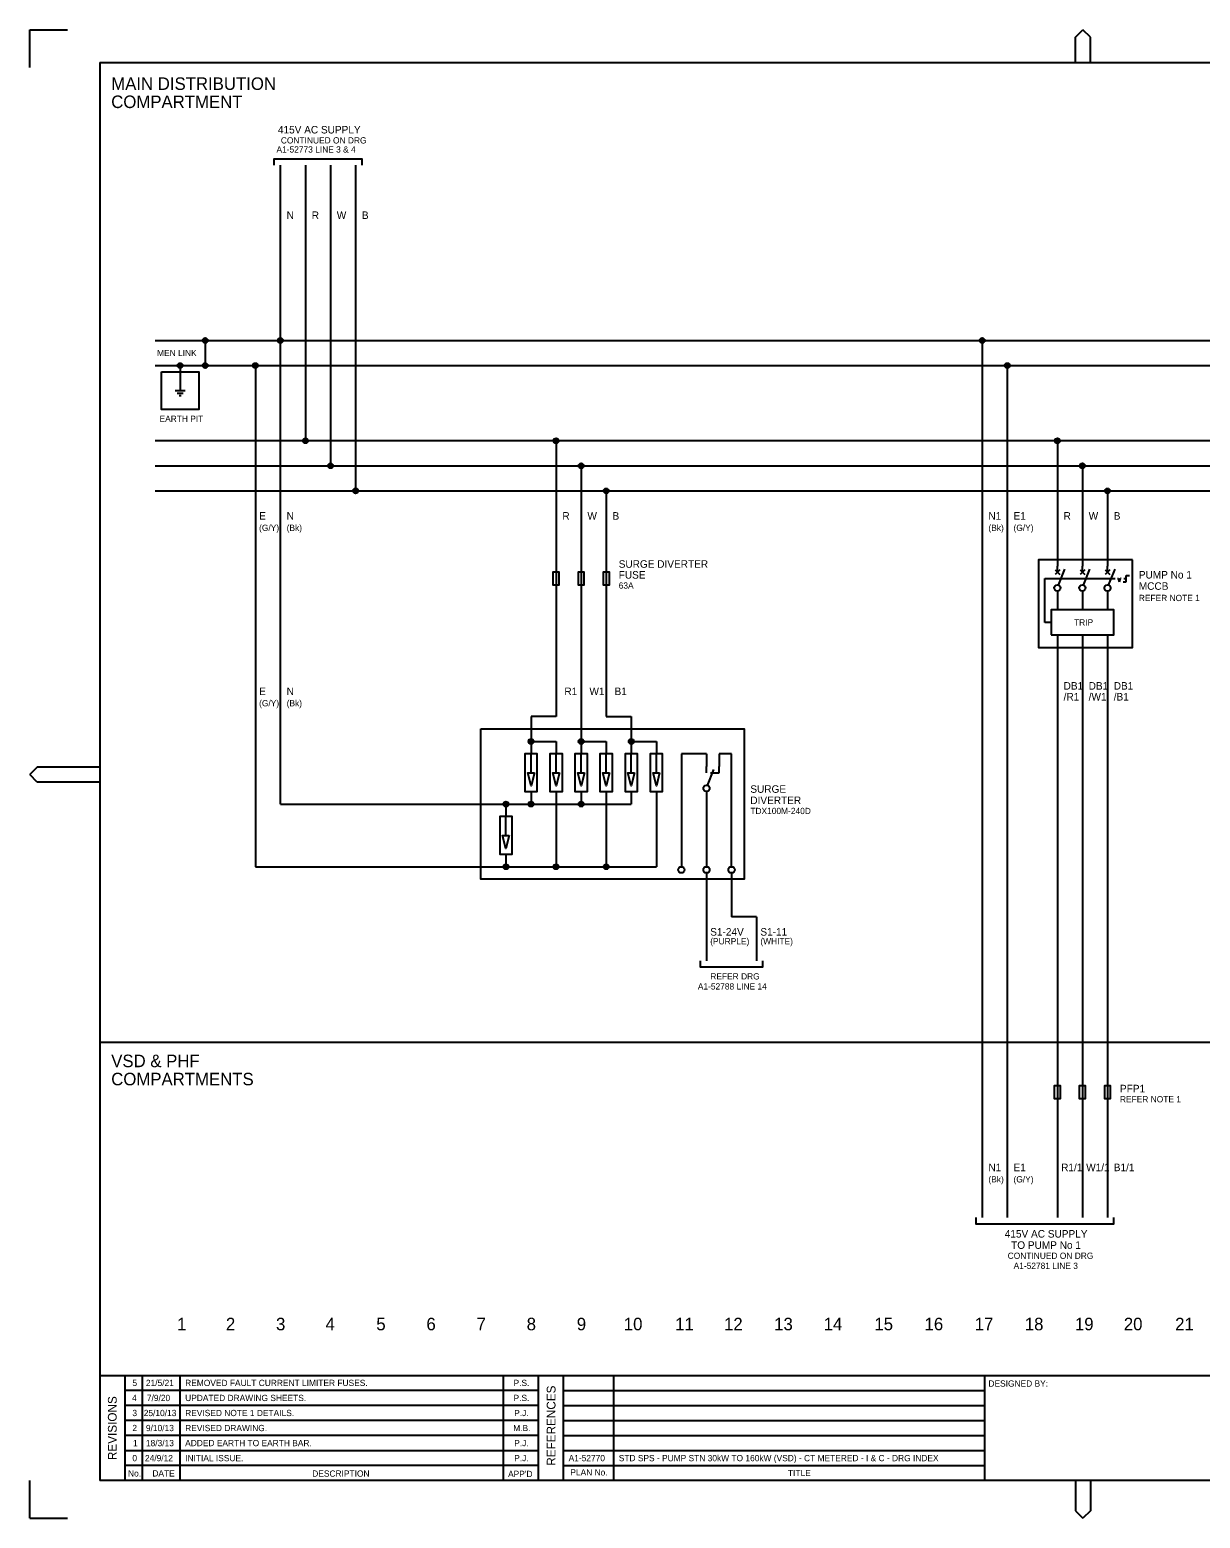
# Model space of a CAD drawing. Extents: x 0 to 841, y 0 to 594.
# Drawn here: x 0 to 467, y 0 to 594 of the extents above; entities that cross this region are included whole.
import ezdxf

# ---------------------------------------------------------------- set-up
doc = ezdxf.new("R2010")
doc.units = 0
for name, color, linetype in [('A1BORDER', 7, 'Continuous'), ('Level 1', 7, 'Continuous'), ('Level 10', 7, 'Continuous')]:
    doc.layers.add(name, color=color, linetype=linetype)

msp = doc.modelspace()

# ---------------------------------------------------------------- linework, layer by layer
at = {"layer": 'A1BORDER'}
for p, q in [((0, 594), (15, 594)), ((0, 579), (0, 594)), ((417.19, 591), (420.19, 594)), ((423.19, 591), (420.19, 594)), ((417.19, 581), (417.19, 591)), ((423.19, 581), (423.19, 591)), ((28, 581), (829, 581)), ((28, 581), (28, 15)), ((3, 299.76), (0, 296.76)), ((28, 299.76), (3, 299.76)), ((3, 293.76), (0, 296.76)), ((28, 293.76), (3, 293.76)), ((28, 57), (829, 57)), ((38, 15), (38, 57)), ((45, 15), (45, 57)), ((60, 15), (60, 57)), ((189, 15), (189, 57)), ((203, 15), (203, 57)), ((213, 15), (213, 57)), ((233, 15), (233, 57)), ((381, 15), (381, 57)), ((203, 51), (38, 51)), ((213, 51), (381, 51)), ((203, 45), (38, 45)), ((213, 45), (381, 45)), ((203, 39), (38, 39)), ((213, 39), (381, 39)), ((203, 33), (38, 33)), ((213, 33), (381, 33)), ((38, 27), (203, 27)), ((213, 27), (381, 27)), ((203, 21), (38, 21)), ((213, 21), (381, 21)), ((0, 0), (0, 15)), ((829, 15), (28, 15)), ((417.19, 15), (417.19, 3)), ((423.19, 15), (423.19, 3)), ((0, 0), (15, 0)), ((417.19, 3), (420.19, 0)), ((423.19, 3), (420.19, 0))]:
    msp.add_line(p, q, dxfattribs=at)
at = {"layer": 'Level 1'}
for p, q in [((100, 285), (100, 540)), ((110, 540), (110, 430)), ((120, 540), (120, 420)), ((130, 540), (130, 410)), ((50, 470), (800, 470)), ((70, 470), (70, 460)), ((380, 470), (380, 120)), ((50, 460), (800, 460)), ((60, 460), (60, 450)), ((90, 460.00001), (90, 260)), ((390, 460), (390, 120)), ((800, 430), (50, 430)), ((210, 430), (210, 320)), ((410, 430), (410, 380)), ((50, 420), (800, 420)), ((220, 420), (220, 305.00001)), ((420, 420), (420, 380)), ((50, 410), (800, 410)), ((230, 410), (230, 320)), ((430, 410), (430, 380)), ((405, 357.5), (405, 375)), ((405, 375), (411.5, 375)), ((409.06, 378.44), (410.94, 376.56)), ((410.94, 378.44), (409.06, 376.56)), ((410, 377.5), (410, 380)), ((410.46, 372.41), (413, 378.75)), ((411.5, 375), (431.5, 375)), ((419.06, 378.44), (420.94, 376.56)), ((420.94, 378.44), (419.06, 376.56)), ((420, 377.5), (420, 380)), ((420.46, 372.41), (423, 378.75)), ((429.06, 378.44), (430.94, 376.56)), ((430.94, 378.44), (429.06, 376.56)), ((430, 377.5), (430, 380)), ((430.46, 372.41), (433, 378.75)), ((410, 370), (410, 362.5)), ((420, 370), (420, 362.5)), ((430, 370), (430, 362.5)), ((407.5, 357.5), (405, 357.5)), ((410, 352.5), (410, 120)), ((420, 352.5), (420, 120)), ((430, 352.5), (430, 120)), ((210, 320.00001), (200, 320.00001)), ((200, 320.00001), (200, 305)), ((230, 320.00001), (240, 320.00001)), ((240, 320.00001), (240, 305.00001)), ((200, 310.00001), (210, 310.00001)), ((210, 310.00001), (210, 305)), ((220, 310.00002), (230, 310.00002)), ((230, 310.00002), (230, 305.00001)), ((240, 310.00002), (250, 310.00002)), ((250, 310.00002), (250, 305.00001)), ((200, 297.5), (200, 305)), ((210, 297.5), (210, 305)), ((220, 297.50001), (220, 305.00001)), ((230, 297.50001), (230, 305.00001)), ((240, 297.50001), (240, 305.00001)), ((250, 297.50001), (250, 305.00001)), ((260, 305), (260, 260)), ((270, 305), (260, 305)), ((270, 305), (270, 300)), ((280, 305), (275, 305)), ((275, 305), (275, 300)), ((280, 259.99999), (280, 305)), ((200, 290), (200, 285)), ((210, 290), (210, 260)), ((220, 290.00001), (220, 285.00001)), ((230, 290.00001), (230, 260)), ((240, 290.00001), (240, 285)), ((250, 290.00001), (250, 260)), ((270, 290), (270, 259.99999)), ((100, 285), (240, 285)), ((190, 285), (190, 280)), ((190, 272.5), (190, 280)), ((190, 265), (190, 260)), ((90, 260), (250, 260)), ((270, 257.49999), (270, 222.5)), ((280, 257.5), (280, 240)), ((290, 239.99999), (280, 239.99999)), ((290, 239.99999), (290, 222.49999)), ((28, 190), (829, 190))]:
    msp.add_line(p, q, dxfattribs=at)
for points in [[(97.5, 540), (97.5, 542.5), (132.5, 542.5), (132.5, 540)], [(267.5, 222.5), (267.5, 220), (292.5, 220), (292.5, 222.5)], [(377.5, 120), (377.5, 117.5), (432.5, 117.5), (432.5, 120)]]:
    msp.add_lwpolyline(points, dxfattribs=at)
for points in [[(52.5, 457.5), (67.5, 457.5), (67.5, 442.5), (52.5, 442.5)], [(440, 382.5), (402.5, 382.5), (402.5, 347.5), (440, 347.5)], [(407.5, 352.5), (432.5, 352.5), (432.5, 362.5), (407.5, 362.5)], [(180, 315), (285, 315), (285, 254.99999), (180, 254.99999)], [(201.32, 297.5), (200, 292.26), (198.68, 297.5)], [(211.32, 297.5), (210, 292.26), (208.68, 297.5)], [(221.32, 297.50001), (220, 292.26001), (218.68, 297.50001)], [(231.32, 297.50001), (230, 292.26001), (228.68, 297.50001)], [(241.32, 297.50001), (240, 292.26001), (238.68, 297.50001)], [(251.32, 297.50001), (250, 292.26001), (248.68, 297.50001)], [(191.32, 272.5), (190, 267.26), (188.68, 272.5)]]:
    msp.add_lwpolyline(points, close=True, dxfattribs=at)
for centre in [(410, 371.25), (420, 371.25), (430, 371.25)]:
    msp.add_circle(centre, 1.25, dxfattribs=at)
at = {"layer": 'Level 10'}
for p, q in [((69.01, 470.1), (70.99, 470.1)), ((69.02, 469.8), (70.98, 469.8)), ((69.08, 470.4), (70.92, 470.4)), ((69.13, 469.5), (70.87, 469.5)), ((69.29, 470.7), (70.71, 470.7)), ((70, 471), (70, 471)), ((99.01, 470.1), (100.99, 470.1)), ((99.02, 469.8), (100.98, 469.8)), ((99.08, 470.4), (100.92, 470.4)), ((99.13, 469.5), (100.87, 469.5)), ((99.29, 470.7), (100.71, 470.7)), ((100, 471), (100, 471)), ((379.01, 470.1), (380.99, 470.1)), ((379.02, 469.8), (380.98, 469.8)), ((379.08, 470.4), (380.92, 470.4)), ((379.13, 469.5), (380.87, 469.5)), ((379.29, 470.7), (380.71, 470.7)), ((380, 471), (380, 471)), ((69.4, 469.2), (70.6, 469.2)), ((99.4, 469.2), (100.6, 469.2)), ((379.4, 469.2), (380.6, 469.2)), ((59.01, 460.1), (60.99, 460.1)), ((59.02, 459.8), (60.98, 459.8)), ((59.08, 460.4), (60.92, 460.4)), ((59.13, 459.5), (60.87, 459.5)), ((59.29, 460.7), (60.71, 460.7)), ((59.4, 459.2), (60.6, 459.2)), ((60, 461), (60, 461)), ((69.01, 460.1), (70.99, 460.1)), ((69.02, 459.8), (70.98, 459.8)), ((69.08, 460.4), (70.92, 460.4)), ((69.13, 459.5), (70.87, 459.5)), ((69.29, 460.7), (70.71, 460.7)), ((69.4, 459.2), (70.6, 459.2)), ((70, 461), (70, 461)), ((89.01, 460.10001), (90.99, 460.10001)), ((89.02, 459.80001), (90.98, 459.80001)), ((89.08, 460.40001), (90.92, 460.40001)), ((89.13, 459.50001), (90.87, 459.50001)), ((89.29, 460.70001), (90.71, 460.70001)), ((89.4, 459.20001), (90.6, 459.20001)), ((90, 461.00001), (90, 461.00001)), ((389.01, 460.1), (390.99, 460.1)), ((389.02, 459.8), (390.98, 459.8)), ((389.08, 460.4), (390.92, 460.4)), ((389.13, 459.5), (390.87, 459.5)), ((389.29, 460.7), (390.71, 460.7)), ((389.4, 459.2), (390.6, 459.2)), ((390, 461), (390, 461)), ((58, 450), (62, 450)), ((58.8, 449), (61.2, 449)), ((59.6, 448), (60.4, 448)), ((109.01, 430.1), (110.99, 430.1)), ((109.02, 429.8), (110.98, 429.8)), ((109.08, 430.4), (110.92, 430.4)), ((109.13, 429.5), (110.87, 429.5)), ((109.29, 430.7), (110.71, 430.7)), ((109.4, 429.2), (110.6, 429.2)), ((110, 431), (110, 431)), ((209.01, 430.1), (210.99, 430.1)), ((209.02, 429.8), (210.98, 429.8)), ((209.08, 430.4), (210.92, 430.4)), ((209.13, 429.5), (210.87, 429.5)), ((209.29, 430.7), (210.71, 430.7)), ((209.4, 429.2), (210.6, 429.2)), ((210, 431), (210, 431)), ((409.01, 430.1), (410.99, 430.1)), ((409.02, 429.8), (410.98, 429.8)), ((409.08, 430.4), (410.92, 430.4)), ((409.13, 429.5), (410.87, 429.5)), ((409.29, 430.7), (410.71, 430.7)), ((409.4, 429.2), (410.6, 429.2)), ((410, 431), (410, 431)), ((119.01, 420.1), (120.99, 420.1)), ((119.02, 419.8), (120.98, 419.8)), ((119.08, 420.4), (120.92, 420.4)), ((119.13, 419.5), (120.87, 419.5)), ((119.29, 420.7), (120.71, 420.7)), ((119.4, 419.2), (120.6, 419.2)), ((120, 421), (120, 421)), ((219.01, 420.1), (220.99, 420.1)), ((219.02, 419.8), (220.98, 419.8)), ((219.08, 420.4), (220.92, 420.4)), ((219.13, 419.5), (220.87, 419.5)), ((219.29, 420.7), (220.71, 420.7)), ((219.4, 419.2), (220.6, 419.2)), ((220, 421), (220, 421)), ((419.01, 420.1), (420.99, 420.1)), ((419.02, 419.8), (420.98, 419.8)), ((419.08, 420.4), (420.92, 420.4)), ((419.13, 419.5), (420.87, 419.5)), ((419.29, 420.7), (420.71, 420.7)), ((419.4, 419.2), (420.6, 419.2)), ((420, 421), (420, 421)), ((129.01, 410.1), (130.99, 410.1)), ((129.08, 410.4), (130.92, 410.4)), ((129.29, 410.7), (130.71, 410.7)), ((130, 411), (130, 411)), ((229.01, 410.1), (230.99, 410.1)), ((229.08, 410.4), (230.92, 410.4)), ((229.29, 410.7), (230.71, 410.7)), ((230, 411), (230, 411)), ((429.01, 410.1), (430.99, 410.1)), ((429.08, 410.4), (430.92, 410.4)), ((429.29, 410.7), (430.71, 410.7)), ((430, 411), (430, 411)), ((129.02, 409.8), (130.98, 409.8)), ((129.13, 409.5), (130.87, 409.5)), ((129.4, 409.2), (130.6, 409.2)), ((229.02, 409.8), (230.98, 409.8)), ((229.13, 409.5), (230.87, 409.5)), ((229.4, 409.2), (230.6, 409.2)), ((429.02, 409.8), (430.98, 409.8)), ((429.13, 409.5), (430.87, 409.5)), ((429.4, 409.2), (430.6, 409.2)), ((431.5, 375), (433, 375)), ((434, 375), (434.33, 375)), ((434.75, 373.75), (434.33, 375)), ((434.75, 373.75), (435.17, 375)), ((435.5, 375), (435.17, 375)), ((436.5, 375), (437.5, 375)), ((437.5, 373.75), (437.5, 376.25)), ((437.5, 376.25), (438.75, 376.25)), ((436.25, 373.75), (437.5, 373.75)), ((199.01, 310.1), (200.99, 310.1)), ((199.02, 309.8), (200.98, 309.8)), ((199.08, 310.4), (200.92, 310.4)), ((199.13, 309.5), (200.87, 309.5)), ((199.29, 310.7), (200.71, 310.7)), ((199.4, 309.2), (200.6, 309.2)), ((200, 311), (200, 311)), ((219.01, 310.10001), (220.99, 310.10001)), ((219.02, 309.80001), (220.98, 309.80001)), ((219.08, 310.40001), (220.92, 310.40001)), ((219.13, 309.50001), (220.87, 309.50001)), ((219.29, 310.70001), (220.71, 310.70001)), ((219.4, 309.20001), (220.6, 309.20001)), ((220, 311.00001), (220, 311.00001)), ((239.01, 310.10001), (240.99, 310.10001)), ((239.02, 309.80001), (240.98, 309.80001)), ((239.08, 310.40001), (240.92, 310.40001)), ((239.13, 309.50001), (240.87, 309.50001)), ((239.29, 310.70001), (240.71, 310.70001)), ((239.4, 309.20001), (240.6, 309.20001)), ((240, 311.00001), (240, 311.00001)), ((270, 297.5), (270, 300)), ((270.46, 292.41), (273, 298.75)), ((271.63, 297.5), (275, 297.5)), ((275, 297.5), (275, 300)), ((189.08, 285.4), (190.92, 285.4)), ((189.29, 285.7), (190.71, 285.7)), ((190, 286), (190, 286)), ((199.08, 285.4), (200.92, 285.4)), ((199.29, 285.7), (200.71, 285.7)), ((200, 286), (200, 286)), ((219.08, 285.40001), (220.92, 285.40001)), ((219.29, 285.70001), (220.71, 285.70001)), ((220, 286.00001), (220, 286.00001)), ((189.01, 285.1), (190.99, 285.1)), ((189.02, 284.8), (190.98, 284.8)), ((189.13, 284.5), (190.87, 284.5)), ((189.4, 284.2), (190.6, 284.2)), ((199.01, 285.1), (200.99, 285.1)), ((199.02, 284.8), (200.98, 284.8)), ((199.13, 284.5), (200.87, 284.5)), ((199.4, 284.2), (200.6, 284.2)), ((219.01, 285.10001), (220.99, 285.10001)), ((219.02, 284.80001), (220.98, 284.80001)), ((219.13, 284.50001), (220.87, 284.50001)), ((219.4, 284.20001), (220.6, 284.20001)), ((189.01, 260.1), (190.99, 260.1)), ((189.02, 259.8), (190.98, 259.8)), ((189.08, 260.4), (190.92, 260.4)), ((189.13, 259.5), (190.87, 259.5)), ((189.29, 260.7), (190.71, 260.7)), ((189.4, 259.2), (190.6, 259.2)), ((190, 261), (190, 261)), ((209.01, 260.1), (210.99, 260.1)), ((209.02, 259.8), (210.98, 259.8)), ((209.08, 260.4), (210.92, 260.4)), ((209.13, 259.5), (210.87, 259.5)), ((209.29, 260.7), (210.71, 260.7)), ((209.4, 259.2), (210.6, 259.2)), ((210, 261), (210, 261)), ((229.01, 260.1), (230.99, 260.1)), ((229.02, 259.8), (230.98, 259.8)), ((229.08, 260.4), (230.92, 260.4)), ((229.13, 259.5), (230.87, 259.5)), ((229.29, 260.7), (230.71, 260.7)), ((229.4, 259.2), (230.6, 259.2)), ((230, 261), (230, 261))]:
    msp.add_line(p, q, dxfattribs=at)
for points in [[(210, 372.5), (211.25, 372.5), (211.25, 377.5), (208.75, 377.5), (208.75, 372.5), (210, 372.5)], [(220, 372.5), (221.25, 372.5), (221.25, 377.5), (218.75, 377.5), (218.75, 372.5), (220, 372.5)], [(230, 372.5), (231.25, 372.5), (231.25, 377.5), (228.75, 377.5), (228.75, 372.5), (230, 372.5)], [(200, 305), (197.5, 305), (197.5, 290), (202.5, 290), (202.5, 305), (200, 305)], [(210, 305), (207.5, 305), (207.5, 290), (212.5, 290), (212.5, 305), (210, 305)], [(220, 305.00001), (217.5, 305.00001), (217.5, 290.00001), (222.5, 290.00001), (222.5, 305.00001), (220, 305.00001)], [(230, 305.00001), (227.5, 305.00001), (227.5, 290.00001), (232.5, 290.00001), (232.5, 305.00001), (230, 305.00001)], [(240, 305.00001), (237.5, 305.00001), (237.5, 290.00001), (242.5, 290.00001), (242.5, 305.00001), (240, 305.00001)], [(250, 305.00001), (247.5, 305.00001), (247.5, 290.00001), (252.5, 290.00001), (252.5, 305.00001), (250, 305.00001)], [(190, 280), (187.5, 280), (187.5, 265), (192.5, 265), (192.5, 280), (190, 280)], [(410, 167.5), (411.25, 167.5), (411.25, 172.5), (408.75, 172.5), (408.75, 167.5), (410, 167.5)], [(420, 167.5), (421.25, 167.5), (421.25, 172.5), (418.75, 172.5), (418.75, 167.5), (420, 167.5)], [(430, 167.5), (431.25, 167.5), (431.25, 172.5), (428.75, 172.5), (428.75, 167.5), (430, 167.5)]]:
    msp.add_lwpolyline(points, dxfattribs=at)
for centre, radius in [((70, 470), 1), ((100, 470), 1), ((380, 470), 1), ((60, 460), 1), ((70, 460), 1), ((90, 460.00001), 1), ((390, 460), 1), ((110, 430), 1), ((210, 430), 1), ((410, 430), 1), ((120, 420), 1), ((220, 420), 1), ((420, 420), 1), ((130, 410), 1), ((230, 410), 1), ((430, 410), 1), ((200, 310), 1), ((220, 310.00001), 1), ((240, 310.00001), 1), ((270, 291.25), 1.25), ((190, 285), 1), ((200, 285), 1), ((220, 285.00001), 1), ((190, 260), 1), ((210, 260), 1), ((230, 260), 1), ((260, 258.74999), 1.25), ((270, 258.74999), 1.25), ((280, 258.74999), 1.25)]:
    msp.add_circle(centre, radius, dxfattribs=at)

# ---------------------------------------------------------------- texts
at = {"layer": 'A1BORDER'}
for s, height, p in [('DESIGNED BY:', 2.5, (382.5, 52.5)), ('No.', 2.50002, (39.21, 16.65)), ('DATE', 2.50002, (48.92, 16.65)), ('DESCRIPTION', 2.50002, (112.71, 16.57)), ("APP'D", 2.50002, (190.85, 16.44)), ('PLAN No.', 2.50002, (215.69, 17.06)), ('TITLE', 2.50002, (302.5, 16.81))]:
    msp.add_text(s, height=height, dxfattribs=at).set_placement(p)
for s, p in [('REVISIONS', (34.68, 23.2)), ('REFERENCES', (209.76, 20.96))]:
    msp.add_text(s, height=3.49998, rotation=90, dxfattribs=at).set_placement(p)
at = {"layer": 'Level 1'}
for s, height, p in [('MAIN DISTRIBUTION', 5, (32.5, 570)), ('COMPARTMENT', 5, (32.5, 562.76367)), ('415V AC SUPPLY', 3, (99.0127, 552.61819)), ('A1-52773 LINE 3 & 4', 2.50002, (98.43981, 545)), ('CONTINUED ON DRG', 2.50002, (100.18299, 548.61819)), ('N', 3, (102.5, 518.49999)), ('R', 3, (112.5, 518.49999)), ('W', 3, (122.5, 518.49999)), ('B', 3, (132.5, 518.49999)), ('MEN LINK', 2.50002, (50.80555, 463.74999)), ('EARTH PIT', 2.50002, (51.78216, 437.49998)), ('E', 3, (91.5, 398.49999)), ('N', 3, (102.5, 398.49999)), ('R', 3, (212.5, 398.49999)), ('W', 3, (222.5, 398.49999)), ('B', 3, (232.5, 398.49999)), ('N1', 3, (382.5, 398.49999)), ('E1', 3, (392.5, 398.49999)), ('R', 3, (412.5, 398.49999)), ('W', 3, (422.5, 398.49999)), ('B', 3, (432.5, 398.49999)), ('(G/Y)', 2.50002, (91.5, 393.99998)), ('(Bk)', 2.50002, (102.5, 393.99998)), ('(Bk)', 2.50002, (382.5, 393.99998)), ('(G/Y)', 2.50002, (392.5, 393.99998)), ('SURGE DIVERTER', 3, (234.98, 379.30178)), ('FUSE', 3, (234.98, 374.95998)), ('PUMP No 1', 3, (442.5, 375)), ('63A', 2.50002, (234.98, 370.96)), ('REFER NOTE 1', 2.50002, (442.5, 365.99998)), ('MCCB', 3, (442.5, 370.5)), ('DB1', 3, (412.5, 330.67089)), ('DB1', 3, (422.5, 330.67089)), ('DB1', 3, (432.5, 330.67089)), ('E', 3, (91.5, 328.5)), ('N', 3, (102.5, 328.5)), ('R1', 3, (213.30804, 328.5)), ('W1', 3, (223.30804, 328.5)), ('B1', 3, (233.30804, 328.5)), ('/R1', 3, (412.5, 326.32909)), ('/W1', 3, (422.5, 326.32909)), ('/B1', 3, (432.5, 326.32909)), ('(G/Y)', 2.50002, (91.5, 323.99999)), ('(Bk)', 2.50002, (102.5, 323.99999)), ('SURGE', 3, (287.5, 289.5)), ('DIVERTER', 3, (287.5, 285)), ('TDX100M-240D', 2.50002, (287.5, 280.99998)), ('S1-24V', 3, (271.5, 232.49999)), ('S1-11', 3, (291.5, 232.49999)), ('(PURPLE)', 2.50002, (271.5, 228.99997)), ('(WHITE)', 2.50002, (291.5, 228.99997)), ('REFER DRG', 2.50002, (271.53314, 214.99998)), ('A1-52788 LINE 14', 2.50002, (266.55263, 210.99996)), ('VSD & PHF', 5, (32.5, 180)), ('COMPARTMENTS', 5, (32.5, 172.76367)), ('PFP1', 3, (434.98, 169.95998)), ('REFER NOTE 1', 2.50002, (434.98, 165.96)), ('(Bk)', 2.50002, (382.5, 133.99998)), ('N1', 3, (382.5, 138.49999)), ('(G/Y)', 2.50002, (392.5, 133.99998)), ('E1', 3, (392.5, 138.49999)), ('R1/1', 3, (411.5, 138.49999)), ('W1/1', 3, (421.5, 138.49999)), ('B1/1', 3, (432.5, 138.49999)), ('415V AC SUPPLY', 3, (389.0127, 112)), ('TO PUMP No 1', 3, (391.55273, 107.5)), ('CONTINUED ON DRG', 2.50002, (390.18299, 103.49998)), ('A1-52781 LINE 3', 2.50002, (392.54873, 99.49996)), ('1', 4.99998, (58.76, 75)), ('2', 4.99998, (78.26, 75)), ('3', 4.99998, (98.26, 75)), ('4', 4.99998, (118.01, 75)), ('5', 4.99998, (138.26, 75)), ('6', 4.99998, (158.26, 75)), ('7', 4.99998, (178.26, 75)), ('8', 4.99998, (198.26, 75)), ('9', 4.99998, (218.26, 75)), ('10', 4.99998, (237.01, 75)), ('11', 4.99998, (257.51, 75)), ('12', 4.99998, (277.01, 75)), ('13', 4.99998, (297.01, 75)), ('14', 4.99998, (316.76, 75)), ('15', 4.99998, (337.01, 75)), ('16', 4.99998, (357.01, 75)), ('17', 4.99998, (377.01, 75)), ('18', 4.99998, (397.01, 75)), ('19', 4.99998, (417.01, 75)), ('20', 4.99998, (436.52, 75)), ('21', 4.99998, (457.01, 75)), ('5', 2.50002, (40.94, 52.75)), ('21/5/21', 2.50002, (46.34256, 52.75)), ('REMOVED FAULT CURRENT LIMITER FUSES.', 2.50002, (62, 52.75)), ('P.S.', 2.50002, (193.01549, 52.75)), ('4', 2.50002, (40.81549, 46.75)), ('7/9/20', 2.50002, (46.7161, 46.75)), ('UPDATED DRAWING SHEETS.', 2.50002, (62, 46.75)), ('P.S.', 2.50002, (193.01549, 46.75)), ('3', 2.50002, (40.94, 40.75)), ('25/10/13', 2.50002, (45.47097, 40.75)), ('REVISED NOTE 1 DETAILS.', 2.50002, (62, 40.75)), ('P.J.', 2.50002, (193.26451, 40.75)), ('2', 2.50002, (40.94, 34.75)), ('9/10/13', 2.50002, (46.34256, 34.75)), ('REVISED DRAWING.', 2.50002, (62, 34.75)), ('M.B.', 2.50002, (192.89097, 34.75)), ('1', 2.50002, (41.18903, 28.75)), ('18/3/13', 2.50002, (46.34256, 28.75)), ('ADDED EARTH TO EARTH BAR.', 2.50002, (62, 28.75)), ('P.J.', 2.50002, (193.26451, 28.75)), ('0', 2.50002, (40.94, 22.75)), ('24/9/12', 2.50002, (45.96903, 22.75)), ('INITIAL ISSUE.', 2.50002, (62, 22.75)), ('P.J.', 2.50002, (193.26451, 22.75)), ('A1-52770', 2.50002, (215, 22.75)), ('STD SPS - PUMP STN 30kW TO 160kW (VSD) - CT METERED - I & C - DRG INDEX', 2.50002, (235, 22.75))]:
    msp.add_text(s, height=height, dxfattribs=at).set_placement(p)
msp.add_text('TRIP', height=2.50002, rotation=360, dxfattribs=at).set_placement((416.64328, 356.25))

doc.saveas('drawing.dxf')
